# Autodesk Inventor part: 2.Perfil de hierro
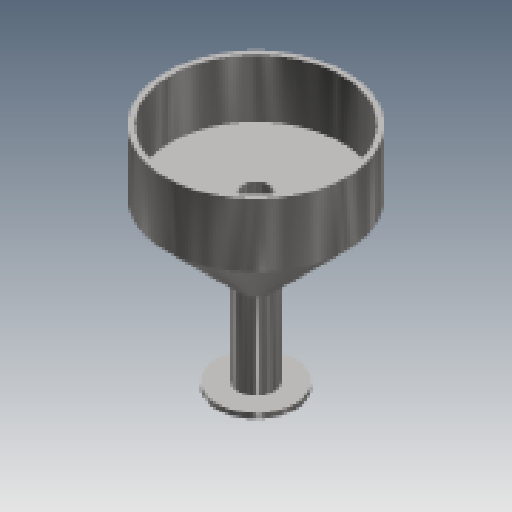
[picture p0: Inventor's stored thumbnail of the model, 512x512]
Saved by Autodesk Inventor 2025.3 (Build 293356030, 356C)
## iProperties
Created: 2025-10
Part Number: 2.Perfil de hierro
Material: Hierro, fundido
Document SubType Name: Modeling
Designer: User
Density: 7.15 g/cm^3
Appearance: Inoxidable - Bruñido
Author: User
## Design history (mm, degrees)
sketch "Boceto1"
  geometry: L1 (-17, -90)-(-17, 60); L2 (-17, 60)-(-86, 60); L3 (-86, 60)-(-86, 120); L4 (-17, -90)-(-37, -90); L5 (-81, 120)-(-81, 65); L6 (-81, 65)-(-12, 65); L7 (-12, 65)-(-12, -95); L8 (-12, -95)-(-37, -95); L9 (-86, 120)-(-81, 120); L10 (-37, -95)-(-37, -90); L11 (0, -138)-(0, 163) reference; L12 (-86, 60)-(-17, -9); 1 further point
  constraints: 22 end point, 5 perpendicular, 2 horizontal, 1 point on line, 1 vertical, 3 other
  dimensions: "d0" = 17 distance from line of point (0, 0) L1; "d1" = 150 distance of L1.start L1.end; "d2" = 69 distance of L1.end L2.end; "d3" = 20 distance of L1.start L4.end; "d4" = 90 distance from line of point (0, 0) L4; "d5" = 60 distance of L2.end L3.end; "d6" = 5 distance between parallel lines of L2 L6; "d9" = 45 deg angle of L1 L12
revolve "Revolución1" sketch "Boceto1" stored, may be unused: angle "d7" = 360 deg
node "Sólido1"
node "Acabados"
node "Finish1" dims "Finish1_Area" = 14389.0648
